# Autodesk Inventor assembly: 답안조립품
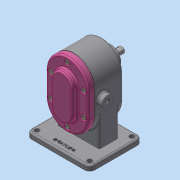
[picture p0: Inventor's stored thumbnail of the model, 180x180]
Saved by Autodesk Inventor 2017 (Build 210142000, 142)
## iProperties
Part Number: 답안조립품
Material: 일반
Document SubType Name: Assembly
Designer: 222
Author: 222
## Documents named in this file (11)
- C:\Users\222\Desktop\700906V1013\답안조립품.iam
- C:\Users\222\Desktop\700906V1013\본체.ipt
- C:\Users\222\Desktop\700906V1013\오일 실 16 28 7.ipt
- C:\Users\222\Desktop\700906V1013\메인축.ipt
- C:\Users\222\Desktop\700906V1013\키 6 x 6 x 18.ipt
- C:\Users\222\Desktop\700906V1013\베어링부시.ipt
- C:\Users\222\Desktop\700906V1013\커버.ipt
- C:\Users\222\Desktop\700906V1013\스퍼기어.ipt
- C:\Users\222\Desktop\700906V1013\서브축.ipt
- C:\Users\222\Desktop\700906V1013\개스킷.ipt
- C:\Users\222\Desktop\700906V1013\볼트 M5.ipt
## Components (1 placed, 1 different names)
1. 개스킷:1
